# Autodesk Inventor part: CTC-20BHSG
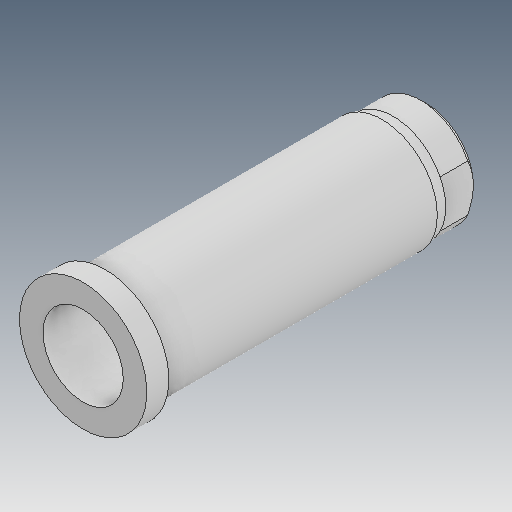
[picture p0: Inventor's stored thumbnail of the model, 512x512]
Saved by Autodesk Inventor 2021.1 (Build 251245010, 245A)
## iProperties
Created: 2018-08
Part Number: CTC-20BHSG
Material: Ogólny
Document SubType Name: Modeling
Designer: user
Density: 1 g/cm^3
Appearance: Domyślna
Author: user
Revision Number: ÈÎºÎ
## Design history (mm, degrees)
feature "ÇÐ³ý-À­Éì3"
node "Bryła1"
